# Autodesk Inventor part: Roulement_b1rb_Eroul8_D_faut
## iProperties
Created: 2011-10
Part Number: Roulement_b1rb_Eroul8_D_faut
Document SubType Name: Modeling
Designer: Bruno
Author: Bruno
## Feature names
1. Base1
